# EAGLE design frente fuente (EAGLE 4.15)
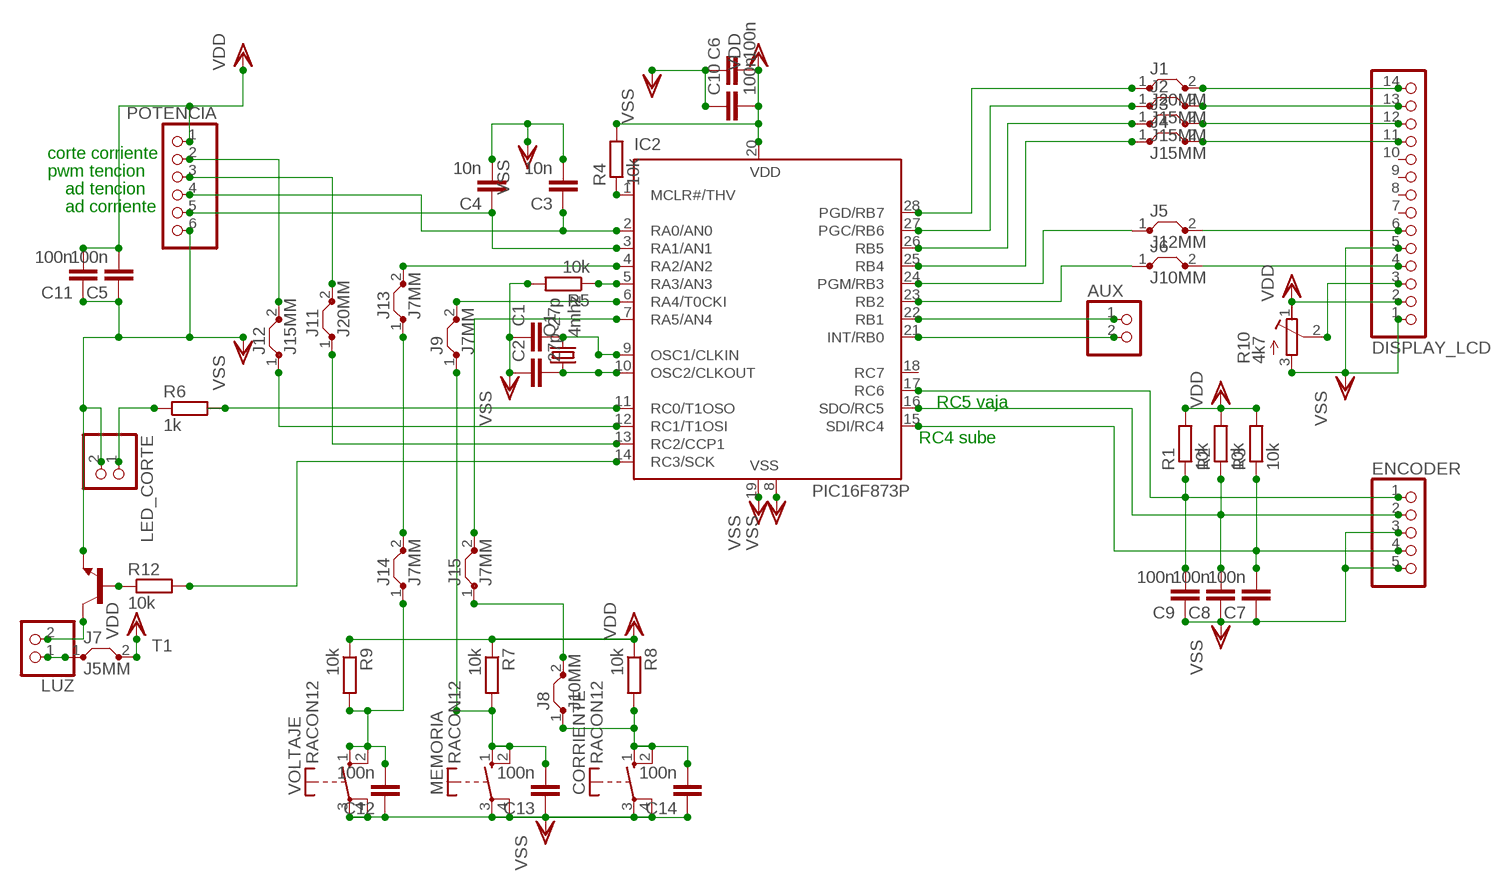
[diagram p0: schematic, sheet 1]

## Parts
AUX  PINHD-1X2  [1X02]
C1  27p  C2.5/2  [C2.5-2]
C2  27p  C2,5-3  [C2.5-3]
C3  10n  C5/2.5  [C5B2.5]
C4  10n  C5/2.5  [C5B2.5]
C5  100n  C5/2.5  [C5B2.5]
C6  100n  C5/2.5  [C5B2.5]
C7  100n  C5/2.5  [C5B2.5]
C8  100n  C5/2.5  [C5B2.5]
C9  100n  C5/2.5  [C5B2.5]
C10  100n  C2,5-3  [C2.5-3]
C11  100n  C5/2.5  [C5B2.5]
C12  100n  C5/2.5  [C5B2.5]
C13  100n  C5/2.5  [C5B2.5]
C14  100n  C5/2.5  [C5B2.5]
CORRIENTE  RACON12  [RACON12]
DISPLAY_LCD  PINHD-1X14  [1X14]
ENCODER  PINHD-1X5  [1X05]
IC2  PIC16F873P  PIC16F872P  [DIL28-3]
J1  J20MM  [20]
J2  J15MM  [15]
J3  J15MM  [15]
J4  J15MM  [15]
J5  J12MM  [12]
J6  J10MM  [10]
J7  J5MM  [05]
J8  J10MM  [10]
J9  J7MM  [07]
J11  J20MM  [20]
J12  J15MM  [15]
J13  J7MM  [07]
J14  J7MM  [07]
J15  J7MM  [07]
LED_CORTE  PINHD-1X2  [1X02]
LUZ  PINHD-1X2  [1X02]
MEMORIA  RACON12  [RACON12]
POTENCIA  PINHD-1X6  [1X06]
Q1  4mhz  CRYTALHC49S  [HC49/S]
R1  10k  R-EU_0204/7  [0204/7]
R2  10k  R-EU_0204/7  [0204/7]
R3  10k  R-EU_0204/7  [0204/7]
R4  10k  R-EU_0204/5  [0204/5]
R5  10k  R-EU_M1206  [M1206]
R6  1k  R-EU_M1206  [M1206]
R7  10k  R-EU_0204/7  [0204/7]
R8  10k  R-EU_0204/7  [0204/7]
R9  10k  R-EU_0204/7  [0204/7]
R10  4k7  R-TRIMMT93XA  [RTRIMT93XA]
R12  10k  R-EU_0204/7  [0204/7]
T1  BC548A-NPN-TO92-EBC  [TO92-EBC]
VOLTAJE  RACON12  [RACON12]

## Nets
N$1: J7.1 LUZ.1
N$2: IC2.4(RA2/AN2) J13.2
N$3: C7.2 ENCODER.4 IC2.15(SDI/RC4) R3.1
N$4: IC2.28(PGD/RB7) J1.1
N$5: IC2.27(PGC/RB6) J2.1
N$6: IC2.26(RB5) J3.1
N$7: IC2.25(RB4) J4.1
N$8: IC2.24(PGM/RB3) J5.1
N$9: IC2.23(RB2) J6.1
N$10: IC2.12(RC1/T1OSI) J12.1
N$11: IC2.13(RC2/CCP1) J11.1
N$13: J12.2 POTENCIA.2
N$14: C2.2 IC2.10(OSC2/CLKOUT) Q1.1
N$15: C1.2 IC2.9(OSC1/CLKIN) Q1.2
N$16: C12.2 J14.1 R9.2 VOLTAJE.1(S) VOLTAJE.2(S)
N$17: IC2.7(RA5/AN4) J15.2
N$18: IC2.1(MCLR#/THV) R4.1
N$19: DISPLAY_LCD.3 R10.2(S)
N$20: IC2.5(RA3/AN3) R5.1
N$21: C13.2 J9.1 MEMORIA.1(S) MEMORIA.2(S) R7.2
N$22: R12.1 T1.B
N$23: LUZ.2 T1.C
N$24: LED_CORTE.1 R6.1
N$26: IC2.11(RC0/T1OSO) R6.2
N$28: AUX.1 IC2.22(RB1)
N$29: AUX.2 IC2.21(INT/RB0)
N$30: IC2.14(RC3/SCK) R12.2
N$32: C9.2 ENCODER.1 IC2.17(RC6) R1.1
N$33: C8.2 ENCODER.2 IC2.16(SDO/RC5) R2.1
N$34: IC2.6(RA4/T0CKI) J9.2
N$35: DISPLAY_LCD.4 J6.2
N$36: DISPLAY_LCD.6 J5.2
N$37: DISPLAY_LCD.11 J4.2
N$38: DISPLAY_LCD.12 J3.2
N$39: DISPLAY_LCD.13 J2.2
N$40: DISPLAY_LCD.14 J1.2
N$41: C4.1 IC2.3(RA1/AN1) POTENCIA.5
N$42: C3.1 IC2.2(RA0/AN0) POTENCIA.4
N$43: J11.2 POTENCIA.3
N$44: C14.2 CORRIENTE.1(S) CORRIENTE.2(S) J8.1 R8.2
N$45: J13.1 J14.2
N$46: J8.2 J15.1
VDD: C5.2 C6.2 C10.2 C11.2 DISPLAY_LCD.2 IC2.20(VDD) J7.2 POTENCIA.1 R1.2 R2.2 R3.2 R4.2 R7.1 R8.1 R9.1 R10.1(A)
VSS: C1.1 C2.1 C3.2 C4.2 C5.1 C6.1 C7.1 C8.1 C9.1 C10.1 C11.1 C12.1 C13.1 C14.1 CORRIENTE.3(P) CORRIENTE.4(P) DISPLAY_LCD.1 DISPLAY_LCD.5 ENCODER.3 ENCODER.5 IC2.8(VSS) IC2.19(VSS) LED_CORTE.2 MEMORIA.3(P) MEMORIA.4(P) POTENCIA.6 R5.2 R10.3(E) T1.E VOLTAJE.3(P) VOLTAJE.4(P)
Unconnected: DISPLAY_LCD.7 DISPLAY_LCD.8 DISPLAY_LCD.9 DISPLAY_LCD.10 IC2.18(RC7)

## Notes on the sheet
- corte corriente
- pwm tencion
- ad tencion
- ad corriente
- RC5 vaja
- RC4 sube

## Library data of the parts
AUX LED_CORTE LUZ = pinhead:PINHD-1X2: PIN HEADER
C1-C14 = capacitor-wima:C: CAPACITOR
CORRIENTE MEMORIA VOLTAJE = switch-misc:RACON12: ITT SWITCH
DISPLAY_LCD = pinhead:PINHD-1X14: PIN HEADER
ENCODER = pinhead:PINHD-1X5: PIN HEADER
IC2 = microchip:PIC16*872: MICROCONTROLLER flash type
J1-J9 J11-J15 = jumper:J: Bridge
POTENCIA = pinhead:PINHD-1X6: PIN HEADER
Q1 = crystal:CRYTAL: CRYSTAL
R1-R9 R12 = rcl:R-EU_: RESISTOR, European symbol
R10 = rcl:R-TRIMM: Trimm resistor
T1 = transistor:*-NPN-: NPN Transistror

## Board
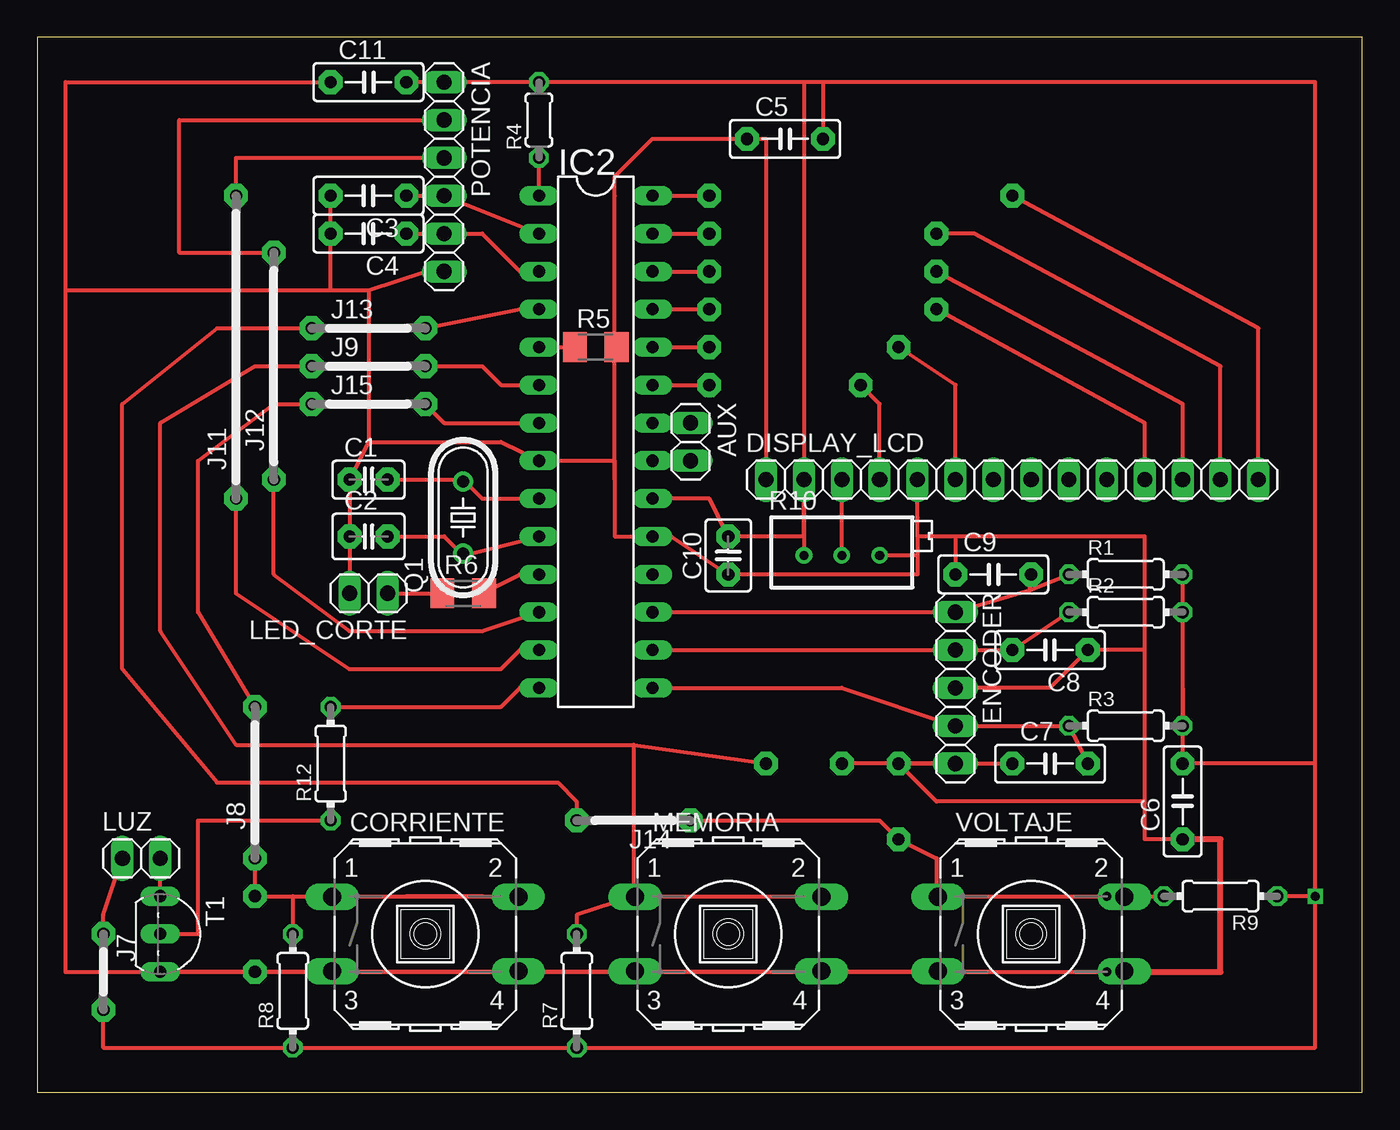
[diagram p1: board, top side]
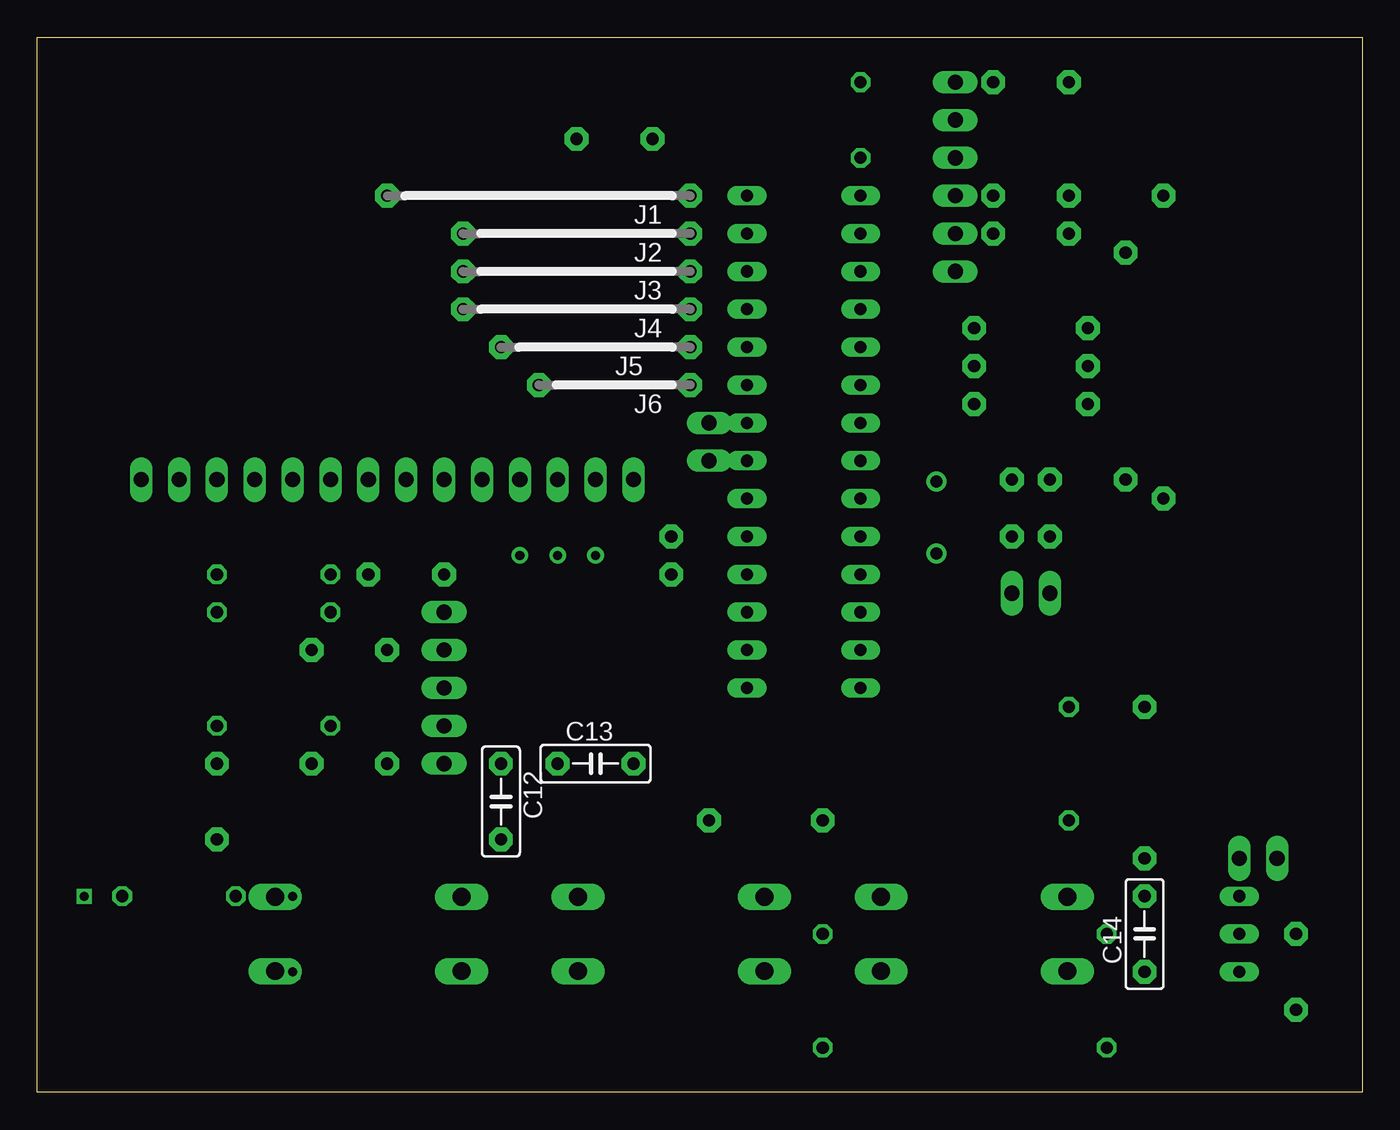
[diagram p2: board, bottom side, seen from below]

Size 88.88 x 70.79 mm. Coordinates in mm from the lower left corner, seen from the top.
Outline: 0,0 88.88,0 88.88,70.79 0,70.79 0,0
Copper layers (1*16): Top 0.035mm / dielectric 1.5mm / Bottom 0.035mm
Design rules "default": minimum track width 10mil, minimum drill 24mil, track to track 8mil, track to pad 8mil, pad to pad 8mil, via to via 8mil, smd to smd 8mil, copper to edge 40mil, drill to drill 8mil, minimum pad ring 10mil, minimum via ring 8mil, stop-mask expansion 4mil, vias tented up to drill 0mil, thermal gap 10mil

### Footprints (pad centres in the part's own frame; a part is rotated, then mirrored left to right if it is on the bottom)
1X02 = drill 1.016 long: 1 -1.27,0; 2 1.27,0
C2.5-2 = drill 0.813 pad 1.6 octagon: 1 -1.27,0; 2 1.27,0
C2.5-3 = drill 0.813 pad 1.6 octagon: 1 -1.27,0; 2 1.27,0
C5B2.5 = drill 0.813 pad 1.6 octagon: 1 -2.54,0; 2 2.54,0
RACON12 = drill 1.194 long: 1 -6.248,2.489; 2 6.248,2.489; 3 -6.248,-2.489; 4 6.248,-2.489
1X14 = drill 1.016 long: 1 -16.51,0; 2 -13.97,0; 3 -11.43,0; 4 -8.89,0; 5 -6.35,0; 6 -3.81,0; 7 -1.27,0; 8 1.27,0; 9 3.81,0; 10 6.35,0; 11 8.89,0; 12 11.43,0; 13 13.97,0; 14 16.51,0
1X05 = drill 1.016 long: 1 -5.08,0; 2 -2.54,0; 3 0,0; 4 2.54,0; 5 5.08,0
DIL28-3 = drill 0.813 long: 1 -16.51,-3.81; 2 -13.97,-3.81; 3 -11.43,-3.81; 4 -8.89,-3.81; 5 -6.35,-3.81; 6 -3.81,-3.81; 7 -1.27,-3.81; 8 1.27,-3.81; 9 3.81,-3.81; 10 6.35,-3.81; 11 8.89,-3.81; 12 11.43,-3.81; 13 13.97,-3.81; 14 16.51,-3.81; 15 16.51,3.81; 16 13.97,3.81; 17 11.43,3.81; 18 8.89,3.81; 19 6.35,3.81; 20 3.81,3.81; 21 1.27,3.81; 22 -1.27,3.81; 23 -3.81,3.81; 24 -6.35,3.81; 25 -8.89,3.81; 26 -11.43,3.81; 27 -13.97,3.81; 28 -16.51,3.81
20 = drill 0.813 pad 1.6 octagon: 1 -10.16,0; 2 10.16,0
15 = drill 0.813 pad 1.6 octagon: 1 -7.62,0; 2 7.62,0
12 = drill 0.813 pad 1.6 octagon: 1 -6.35,0; 2 6.35,0
10 = drill 0.813 pad 1.6 octagon: 1 -5.08,0; 2 5.08,0
05 = drill 0.813 pad 1.6 octagon: 1 -2.54,0; 2 2.54,0
07 = drill 0.813 pad 1.6 octagon: 1 -3.81,0; 2 3.81,0
1X06 = drill 1.016 long: 1 -6.35,0; 2 -3.81,0; 3 -1.27,0; 4 1.27,0; 5 3.81,0; 6 6.35,0
HC49/S = drill 0.813 round: 1 -2.413,0; 2 2.413,0
0204/7 = drill 0.813 octagon: 1 -3.81,0; 2 3.81,0
0204/5 = drill 0.813 octagon: 1 -2.54,0; 2 2.54,0
M1206 = smd 1.6 x 2: 1 -1.4,0; 2 1.4,0
RTRIMT93XA = drill 0.61 round: 1 0,-2.54; 2 0,0; 3 0,2.54
TO92-EBC = drill 0.813 long: B 0,-1.27; C -2.54,-1.27; E 2.54,-1.27

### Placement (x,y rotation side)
AUX  43.81,43.65 270 top
C1  22.22,41.11 0 top
C2  22.22,37.3 0 top
C3  22.22,60.16 180 top
C4  22.22,57.62 180 top
C5  50.16,63.97 0 top
C6  76.83,19.52 90 top
C7  67.94,22.06 0 top
C8  67.94,29.68 180 top
C9  64.13,34.76 0 top
C10  46.35,36.03 90 top
C11  22.22,67.78 0 top
C12  57.78,19.52 270 bottom
C13  51.43,22.06 0 bottom
C14  14.6,10.63 90 bottom
CORRIENTE  26.03,10.63 0 top
DISPLAY_LCD  65.4,41.11 0 top
ENCODER  61.59,27.14 270 top
IC2  37.46,43.65 270 top
J1  55.24,60.16 180 bottom
J2  52.7,57.62 180 bottom
J3  52.7,55.08 180 bottom
J4  52.7,52.54 180 bottom
J5  51.43,50 180 bottom
J6  50.16,47.46 180 bottom
J7  4.44,8.09 270 top
J8  14.6,20.79 90 top
J9  22.22,48.73 0 top
J11  13.33,50 90 top
J12  15.87,48.73 90 top
J13  22.22,51.27 0 top
J14  40,18.25 180 top
J15  22.22,46.19 0 top
LED_CORTE  22.22,33.49 180 top
LUZ  6.98,15.71 0 top
MEMORIA  46.35,10.63 0 top
POTENCIA  27.3,61.43 270 top
Q1  28.57,38.57 90 top
R1  73.02,34.76 0 top
R2  73.02,32.22 0 top
R3  73.02,24.6 0 top
R4  33.65,65.24 90 top
R5  37.46,50 0 top
R6  28.57,33.49 0 top
R7  36.19,6.82 90 top
R8  17.14,6.82 90 top
R9  79.37,13.17 180 top
R10  53.97,36.03 270 top
R12  19.68,22.06 90 top
T1  9.52,10.63 270 top
VOLTAJE  66.67,10.63 0 top

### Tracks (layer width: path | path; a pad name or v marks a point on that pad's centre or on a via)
N$1
  Top 0.254: J7.1 4.44,11.9 LUZ.1
N$2
  Top 0.254: J13.2 32.38,52.54 IC2.4
N$3
  Top 0.254: C7.2 R3.1 ENCODER.4 53.97,27.14 IC2.15
N$4
  Top 0.254: IC2.28 J1.1
N$5
  Top 0.254: IC2.27 J2.1
N$6
  Top 0.254: IC2.26 J3.1
N$7
  Top 0.254: IC2.25 J4.1
N$8
  Top 0.254: IC2.24 J5.1
N$9
  Top 0.254: IC2.23 J6.1
N$10
  Top 0.254: J12.1 15.87,34.76 20.95,30.95 29.84,30.95 IC2.12
N$11
  Top 0.254: J11.1 13.33,33.49 20.95,28.41 31.11,28.41 32.38,29.68 IC2.13
N$13
  Top 0.254: J12.2 9.52,56.35 9.52,65.24 POTENCIA.2
N$14
  Top 0.254: 28.57,36.03 IC2.10 | C2.2 27.3,37.3 28.57,36.03 | 28.57,36.03 Q1.1
N$15
  Top 0.254: 28.57,41.11 29.84,39.84 IC2.9 | C1.2 28.57,41.11 | 28.57,41.11 Q1.2
N$16  (via drill 0.6)
  Top 0.254: v73.02,13.17 R9.2 | v73.02,13.17 VOLTAJE.2 | v60.32,13.17 v71.75,13.17 | v71.75,13.17 v73.02,13.17 | v71.75,13.17 v73.02,13.17 | v71.75,13.17 VOLTAJE.1 v60.32,13.17 | J14.1 56.51,18.25 C12.2 60.32,15.71 v60.32,13.17
N$17
  Top 0.254: IC2.7 27.3,44.92 J15.2
N$18
  Top 0.254: IC2.1 R4.1
N$19
  Top 0.254: R10.2 DISPLAY_LCD.3
N$20
  Top 0.254: 36.19,50 R5.1 IC2.5
N$21
  Top 0.254: 40,13.17 MEMORIA.2 40.05,13.12 | 40,23.33 C13.2 | R7.2 36.19,11.9 40,13.17 | 40,13.17 MEMORIA.1 | J9.1 14.6,48.73 8.25,44.92 8.25,30.95 13.33,23.33 40,23.33 | 40,23.33 40,13.17
N$22
  Top 0.254: R12.1 10.79,18.25 10.79,10.63 T1.B
N$23
  Top 0.254: T1.C LUZ.2
N$24
  Top 0.254: LED_CORTE.1 R6.1 27.3,33.49
N$26
  Top 0.254: R6.2 29.84,33.49 32.38,34.76 IC2.11
N$28
  Top 0.254: IC2.22 AUX.1
N$29
  Top 0.254: IC2.21 AUX.2
N$30
  Top 0.254: R12.2 31.11,25.87 32.38,27.14 IC2.14
N$32
  Top 0.254: IC2.17 ENCODER.1 66.58,33.71 | 66.58,33.71 R1.1 | 66.58,33.71 C9.2
N$33
  Top 0.254: ENCODER.2 C8.2 | C8.2 R2.1 | IC2.16 ENCODER.2 | ENCODER.2 C8.2 | C8.2 R2.1 | C8.2 R2.1 | C8.2 R2.1
N$34
  Top 0.254: J9.2 29.84,48.73 31.11,47.46 IC2.6
N$35
  Top 0.254: J6.2 56.51,46.19 DISPLAY_LCD.4
N$36
  Top 0.254: J5.2 61.59,47.46 DISPLAY_LCD.6
N$37
  Top 0.254: J4.2 74.29,44.92 DISPLAY_LCD.11
N$38
  Top 0.254: J3.2 76.83,46.19 DISPLAY_LCD.12
N$39
  Top 0.254: J2.2 62.86,57.62 79.37,48.73 DISPLAY_LCD.13
N$40
  Top 0.254: J1.2 81.91,51.27 DISPLAY_LCD.14
N$41
  Top 0.254: C4.1 POTENCIA.5 29.84,57.62 32.38,55.08 IC2.3
N$42
  Top 0.254: IC2.2 POTENCIA.4 C3.1
N$43
  Top 0.254: J11.2 13.33,62.7 POTENCIA.3
N$44
  Top 0.254: C14.2 17.14,13.17 R8.2 | C14.2 J8.1 | 24.76,13.17 31.11,13.17 CORRIENTE.1 | C14.2 J8.1 | 29.84,13.17 24.76,13.17 | 24.76,13.17 33.65,13.17 CORRIENTE.2 29.84,13.17 | C14.2 29.84,13.17 | C14.2 J8.1
N$45
  Top 0.254: J13.1 12.06,51.27 5.71,46.19 5.71,28.41 12.06,20.79 34.92,20.79 36.19,19.52 J14.2
N$46
  Top 0.254: J15.1 15.87,46.19 10.79,42.38 10.79,32.22 J8.2
VDD  (via drill 0.6)
  Top 0.254: IC2.20 45.08,39.84 C10.2 51.43,37.3 | 51.43,67.78 51.43,37.3 | 51.43,37.3 R10.1 | 51.43,37.3 DISPLAY_LCD.2 | 51.43,67.78 R4.2 POTENCIA.1 C11.2 | R1.2 R2.2 76.83,27.14 | J7.2 4.44,3.01 R8.1 R7.1 85.72,3.01 v85.72,13.17 | 76.83,27.14 C6.2 85.72,22.06 | 76.83,27.14 R3.2 | v85.72,13.17 R9.1 | v85.72,13.17 85.72,22.06 | 52.7,67.78 85.72,67.78 85.72,22.06 | 52.7,67.78 51.43,67.78 | 52.7,67.78 C5.2
VSS  (via drill 0.6)
  Top 0.254: v73.02,8.09 VOLTAJE.4 v71.75,8.09 | v60.32,8.09 53.97,8.09 | v60.32,8.09 64.13,8.09 MEMORIA.4 | v60.32,8.09 VOLTAJE.3 v60.32,8.09 | 46.35,8.09 48.89,8.09 MEMORIA.3 46.35,8.09 | 46.35,8.09 43.81,8.09 CORRIENTE.4 41.27,8.09 31.11,8.09 CORRIENTE.3 28.57,8.09 C14.1 T1.E | v60.32,8.09 61.59,8.09 MEMORIA.4 | v60.32,8.09 v71.75,8.09 | v71.75,8.09 v73.02,8.09 | v71.75,8.09 v73.02,8.09 | 22.22,43.65 31.11,43.65 IC2.8 38.73,42.38 | 22.22,43.65 C1.1 C2.1 LED_CORTE.2 | 59.05,37.3 59.05,38.57 | 59.05,37.3 DISPLAY_LCD.5 | 61.59,37.3 C9.1 | C4.2 C3.2 C4.2 | 1.9,53.81 1.9,67.78 C11.1 | 38.73,50 38.73,60.16 | 74.29,29.68 74.29,37.3 61.59,37.3 | 38.73,42.38 38.73,50 | 38.73,42.38 38.73,41.11 | 38.73,41.11 38.73,37.3 IC2.19 42.54,37.3 C10.1 59.05,34.76 59.05,37.3 | 61.59,37.3 59.05,37.3 | 38.73,50 R5.2 | 59.05,37.3 59.05,36.03 R10.3 | 22.22,53.81 22.22,43.65 | 1.9,53.81 19.68,53.81 | 19.68,53.81 22.22,53.81 | v60.32,8.09 62.86,8.09 MEMORIA.4 | 46.35,8.09 1.9,8.09 1.9,53.81 | 46.35,8.09 v60.32,8.09 | ENCODER.5 C12.1 60.32,19.52 74.29,19.52 74.29,16.98 | ENCODER.5 C7.1 | ENCODER.3 67.94,27.14 C8.1 74.29,29.68 | 74.29,16.98 74.29,29.68 | C6.1 74.29,16.98 | 38.73,60.16 38.73,61.43 | 38.73,42.38 38.73,60.16 | 38.73,41.11 38.73,61.43 | 38.73,61.43 41.27,63.97 C5.1 48.89,63.97 DISPLAY_LCD.1 | ENCODER.5 C13.1 | 22.22,53.81 26.03,55.08 POTENCIA.6 | 19.68,53.81 C4.2
  Top 0.406: C6.1 79.37,16.98 79.37,8.09 v71.75,8.09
